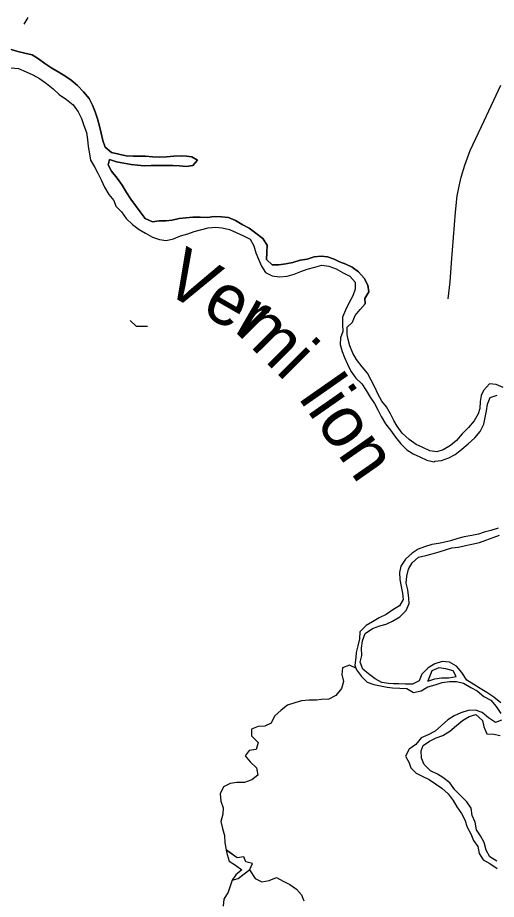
# Model space of a CAD drawing. Extents: x 0 to 34, y 0 to 22.
# Drawn here: x 6.124 to 7.011, y 8.561 to 10.195 of the extents above; entities that cross this region are included whole.
import ezdxf

# ---------------------------------------------------------------- set-up
doc = ezdxf.new("R2010")
doc.units = 0
for name, color, linetype in [('GM_X_City_Street', 7, 'Continuous'), ('GM_X_Major_River', 7, 'Continuous'), ('GM_X_Major_River_Text', 7, 'Continuous'), ('GM_X_Minor_Lake', 7, 'Continuous'), ('GM_X_Minor_River', 7, 'Continuous')]:
    doc.layers.add(name, color=color, linetype=linetype)

msp = doc.modelspace()

# ---------------------------------------------------------------- linework, layer by layer
at = {"layer": 'GM_X_City_Street'}
msp.add_line((6.1365, 10.1828), (6.144, 10.1951), dxfattribs=at)
for points in [[(6.9213, 9.674), (6.925, 9.7052), (6.9277, 9.7408), (6.9311, 9.7875), (6.9351, 9.8347), (6.9383, 9.8647), (6.9415, 9.8829), (6.9454, 9.8991), (6.9525, 9.9213), (6.962, 9.9489), (6.9882, 10.0038), (7.0189, 10.0702)], [(6.3327, 9.6337), (6.3439, 9.6234), (6.3648, 9.6231)]]:
    msp.add_lwpolyline(points, dxfattribs=at)
at = {"layer": 'GM_X_Major_River'}
for points in [[(6.7675, 9.6648), (6.767, 9.6743), (6.7742, 9.687), (6.7729, 9.6991), (6.7656, 9.712), (6.7552, 9.7241), (6.7434, 9.7327), (6.7316, 9.7379), (6.7201, 9.7424), (6.7106, 9.7473), (6.698, 9.7517), (6.6862, 9.7531), (6.6733, 9.7519), (6.6604, 9.7476), (6.6471, 9.7452), (6.6335, 9.7412), (6.6206, 9.7384), (6.6076, 9.7368), (6.5955, 9.7367), (6.5851, 9.7465), (6.5854, 9.7598), (6.5861, 9.7731), (6.578, 9.7856), (6.5653, 9.7954), (6.5527, 9.8048), (6.5397, 9.8119), (6.5275, 9.819), (6.5149, 9.8246), (6.5016, 9.826), (6.4879, 9.8267), (6.4758, 9.8246), (6.4621, 9.8253), (6.4488, 9.8255), (6.4359, 9.8239), (6.4233, 9.823), (6.4101, 9.8199), (6.3987, 9.8186), (6.3865, 9.8181), (6.374, 9.8165), (6.3606, 9.8228), (6.3514, 9.8353), (6.3422, 9.8466), (6.3341, 9.8587), (6.3256, 9.8712), (6.3175, 9.8848), (6.3087, 9.8977), (6.2983, 9.9102), (6.2918, 9.9223), (6.2943, 9.9318), (6.3073, 9.9277), (6.321, 9.9256), (6.3347, 9.9227), (6.3465, 9.9216), (6.3587, 9.9202), (6.3716, 9.9207), (6.3853, 9.9208), (6.3982, 9.921), (6.4115, 9.9207), (6.4237, 9.9201), (6.4366, 9.919), (6.4484, 9.921), (6.457, 9.931), (6.4467, 9.937), (6.4372, 9.9381), (6.4277, 9.9387), (6.4133, 9.9382), (6.4, 9.9373), (6.3874, 9.9365), (6.3737, 9.9371), (6.3612, 9.9381), (6.3509, 9.9384), (6.338, 9.9383), (6.3251, 9.9389), (6.3114, 9.9419), (6.298, 9.9448), (6.2865, 9.955), (6.2823, 9.9675), (6.2787, 9.9808), (6.276, 9.9941), (6.2724, 10.0073), (6.2678, 10.0206), (6.2631, 10.0331), (6.2565, 10.0452), (6.2465, 10.0577), (6.235, 10.069), (6.2232, 10.0792), (6.2117, 10.0871), (6.1995, 10.0946), (6.1876, 10.1017), (6.1746, 10.1103), (6.1632, 10.119), (6.1513, 10.1261), (6.1376, 10.129), (6.1247, 10.1323), (6.1121, 10.136)], [(6.1121, 10.136), (6.1247, 10.1323), (6.1376, 10.129), (6.1513, 10.1261), (6.1632, 10.119), (6.1746, 10.1103), (6.1876, 10.1017), (6.1995, 10.0946), (6.2117, 10.0871), (6.2232, 10.0792), (6.235, 10.069), (6.2465, 10.0577), (6.2565, 10.0452), (6.2631, 10.0331), (6.2678, 10.0206), (6.2724, 10.0073), (6.276, 9.9941), (6.2787, 9.9808), (6.2823, 9.9675), (6.2865, 9.955), (6.298, 9.9448), (6.3114, 9.9419), (6.3251, 9.9389), (6.338, 9.9383), (6.3509, 9.9384), (6.3612, 9.9381), (6.3737, 9.9371), (6.3874, 9.9365), (6.4, 9.9373), (6.4133, 9.9382), (6.4277, 9.9387), (6.4372, 9.9381), (6.4467, 9.937), (6.457, 9.931), (6.4484, 9.921), (6.4366, 9.919), (6.4237, 9.9201), (6.4115, 9.9207), (6.3982, 9.921), (6.3853, 9.9208), (6.3716, 9.9207), (6.3587, 9.9202), (6.3465, 9.9216), (6.3347, 9.9227), (6.321, 9.9256), (6.3073, 9.9277), (6.2943, 9.9318), (6.2918, 9.9223), (6.2983, 9.9102), (6.3087, 9.8977), (6.3175, 9.8848), (6.3256, 9.8712), (6.3341, 9.8587), (6.3422, 9.8466), (6.3514, 9.8353), (6.3606, 9.8228), (6.374, 9.8165), (6.3865, 9.8181), (6.3987, 9.8186), (6.4101, 9.8199), (6.4233, 9.823), (6.4359, 9.8239), (6.4488, 9.8255), (6.4621, 9.8253), (6.4758, 9.8246), (6.4879, 9.8267), (6.5016, 9.826), (6.5149, 9.8246), (6.5275, 9.819), (6.5397, 9.8119), (6.5527, 9.8048), (6.5653, 9.7954), (6.578, 9.7856), (6.5861, 9.7731), (6.5854, 9.7598), (6.5851, 9.7465), (6.5955, 9.7367), (6.6076, 9.7368), (6.6206, 9.7384), (6.6335, 9.7412), (6.6471, 9.7452), (6.6604, 9.7476), (6.6733, 9.7519), (6.6862, 9.7531), (6.698, 9.7517), (6.7106, 9.7473), (6.7201, 9.7424), (6.7316, 9.7379), (6.7434, 9.7327), (6.7552, 9.7241), (6.7656, 9.712), (6.7729, 9.6991), (6.7742, 9.687), (6.767, 9.6743), (6.7675, 9.6648)], [(6.1124, 10.1021), (6.1261, 10.1008), (6.1398, 10.0948), (6.1524, 10.0892), (6.165, 10.0825), (6.178, 10.0731), (6.1902, 10.0633), (6.2014, 10.0524), (6.2147, 10.0433), (6.227, 10.0332), (6.2366, 10.0203), (6.2424, 10.0082), (6.2471, 9.9953), (6.2517, 9.982), (6.2534, 9.9691), (6.2546, 9.9562), (6.2574, 9.9425), (6.2594, 9.9307), (6.2663, 9.9182), (6.2725, 9.9065), (6.2791, 9.8944), (6.2853, 9.8807), (6.2933, 9.8671), (6.3026, 9.8558), (6.3061, 9.8455), (6.3168, 9.835), (6.3253, 9.8229), (6.3371, 9.8116), (6.3494, 9.8026), (6.3612, 9.7954), (6.3742, 9.7883), (6.3868, 9.7839), (6.3993, 9.7821), (6.413, 9.7849), (6.4259, 9.7903), (6.4392, 9.7946), (6.4513, 9.7989), (6.4771, 9.8052), (6.4904, 9.8069), (6.5029, 9.8055), (6.5166, 9.8022), (6.5288, 9.797), (6.5422, 9.7906), (6.5548, 9.7843), (6.5614, 9.7718), (6.5653, 9.7592), (6.5699, 9.7471), (6.5757, 9.7346), (6.5831, 9.7225), (6.5956, 9.7165), (6.6093, 9.7147), (6.623, 9.716), (6.6363, 9.7196), (6.6484, 9.7246), (6.6605, 9.7285), (6.6746, 9.7328), (6.6875, 9.736), (6.7004, 9.7346), (6.7138, 9.7294), (6.7267, 9.7219), (6.7393, 9.7156), (6.7493, 9.7046), (6.749, 9.6917), (6.745, 9.6795), (6.7375, 9.6657), (6.7311, 9.6527), (6.7255, 9.6397), (6.726, 9.626), (6.7265, 9.6135), (6.722, 9.6012), (6.7214, 9.5891), (6.7249, 9.5762), (6.7292, 9.5648), (6.735, 9.5527), (6.7412, 9.5398), (6.7504, 9.5269), (6.7615, 9.5164), (6.7696, 9.5039), (6.7769, 9.4918), (6.785, 9.4797), (6.7912, 9.4683), (6.7974, 9.4554), (6.8054, 9.4422), (6.8143, 9.4301), (6.8239, 9.4172), (6.8335, 9.4048), (6.8446, 9.3938), (6.8568, 9.3863), (6.8691, 9.3807), (6.882, 9.3748), (6.8946, 9.3715)], [(6.1124, 10.1021), (6.1261, 10.1008), (6.1398, 10.0948), (6.1524, 10.0892), (6.165, 10.0825), (6.178, 10.0731), (6.1902, 10.0633), (6.2014, 10.0524), (6.2147, 10.0433), (6.227, 10.0332), (6.2366, 10.0203), (6.2424, 10.0082), (6.2471, 9.9953), (6.2517, 9.982), (6.2534, 9.9691), (6.2546, 9.9562), (6.2574, 9.9425), (6.2594, 9.9307), (6.2663, 9.9182), (6.2725, 9.9065), (6.2791, 9.8944), (6.2853, 9.8807), (6.2933, 9.8671), (6.3026, 9.8558), (6.3061, 9.8455), (6.3168, 9.835), (6.3253, 9.8229), (6.3371, 9.8116), (6.3494, 9.8026), (6.3612, 9.7954), (6.3742, 9.7883), (6.3868, 9.7839), (6.3993, 9.7821), (6.413, 9.7849), (6.4259, 9.7903), (6.4392, 9.7946), (6.4513, 9.7989), (6.4771, 9.8052), (6.4904, 9.8069), (6.5029, 9.8055), (6.5166, 9.8022), (6.5288, 9.797), (6.5422, 9.7906), (6.5548, 9.7843), (6.5614, 9.7718), (6.5653, 9.7592), (6.5699, 9.7471), (6.5757, 9.7346), (6.5831, 9.7225), (6.5956, 9.7165), (6.6093, 9.7147), (6.623, 9.716), (6.6363, 9.7196), (6.6484, 9.7246), (6.6605, 9.7285), (6.6746, 9.7328), (6.6875, 9.736), (6.7004, 9.7346), (6.7138, 9.7294), (6.7267, 9.7219), (6.7393, 9.7156), (6.7493, 9.7046), (6.749, 9.6917), (6.745, 9.6795), (6.7375, 9.6657), (6.7311, 9.6527), (6.7255, 9.6397), (6.726, 9.626), (6.7265, 9.6135), (6.722, 9.6012), (6.7214, 9.5891), (6.7249, 9.5762), (6.7292, 9.5648), (6.735, 9.5527), (6.7412, 9.5398), (6.7504, 9.5269), (6.7615, 9.5164), (6.7696, 9.5039), (6.7769, 9.4918), (6.785, 9.4797), (6.7912, 9.4683), (6.7974, 9.4554), (6.8054, 9.4422), (6.8143, 9.4301), (6.8239, 9.4172), (6.8335, 9.4048), (6.8446, 9.3938), (6.8568, 9.3863), (6.8691, 9.3807), (6.882, 9.3748), (6.8946, 9.3715)], [(7.0231, 9.5096), (7.0101, 9.5152), (6.9976, 9.5162), (6.9866, 9.504), (6.9825, 9.4944), (6.9803, 9.4837), (6.9801, 9.4704), (6.9771, 9.4605), (6.9696, 9.4475), (6.9591, 9.4352), (6.9474, 9.4233), (6.9365, 9.4114), (6.9255, 9.4018), (6.9123, 9.3937), (6.9005, 9.3902), (6.8872, 9.3919), (6.8746, 9.3979), (6.862, 9.4035), (6.849, 9.4133), (6.8364, 9.425), (6.8272, 9.4378), (6.821, 9.448), (6.8144, 9.4605), (6.8071, 9.4734), (6.7983, 9.4844), (6.7913, 9.498), (6.7855, 9.5101), (6.7789, 9.523), (6.772, 9.5359), (6.7624, 9.548), (6.7516, 9.5612), (6.7447, 9.5733), (6.7393, 9.5866), (6.7365, 9.5983), (6.7345, 9.6078), (6.7344, 9.6215), (6.7442, 9.6304), (6.7491, 9.6426), (6.7585, 9.6541), (6.7675, 9.6648)], [(6.8946, 9.3715), (6.8969, 9.373), (6.909, 9.3739), (6.9227, 9.3789), (6.9344, 9.3851), (6.9465, 9.3951), (6.9582, 9.4048), (6.9706, 9.4159), (6.9808, 9.4278), (6.9872, 9.4412), (6.9923, 9.4663), (6.9944, 9.4785), (6.9989, 9.4908), (7.0118, 9.4951)], [(7.0138, 9.2485), (7.0006, 9.2442), (6.9877, 9.241), (6.9778, 9.2375), (6.9649, 9.2351), (6.9512, 9.2327), (6.9391, 9.2292), (6.9258, 9.2252), (6.9129, 9.2221), (6.9034, 9.2205), (6.8909, 9.2181), (6.8777, 9.2141), (6.8659, 9.2099), (6.8549, 9.2021), (6.8425, 9.191), (6.8339, 9.1784), (6.8313, 9.1665), (6.8318, 9.1536), (6.8345, 9.1407), (6.8369, 9.1282), (6.8382, 9.1167), (6.831, 9.1045), (6.8189, 9.0975), (6.8068, 9.0887), (6.7936, 9.0825), (6.7811, 9.0751), (6.7694, 9.0682), (6.7581, 9.0563), (6.757, 9.0433), (6.7541, 9.0304), (6.7512, 9.0182), (6.7501, 9.0086), (6.7483, 8.9949)], [(6.8204, 8.9598), (6.8106, 8.9605), (6.7984, 8.9623), (6.7862, 8.9694), (6.7739, 8.9788), (6.7632, 8.9874), (6.7585, 9.0003), (6.7615, 9.0125), (6.7606, 9.0262), (6.7628, 9.0396), (6.7676, 9.0537), (6.7812, 9.0626), (6.7948, 9.0676), (6.8066, 9.0708), (6.8183, 9.0762), (6.8316, 9.0843), (6.8433, 9.0959), (6.8489, 9.1092), (6.8484, 9.1191), (6.8468, 9.1343), (6.8436, 9.1465), (6.8447, 9.1594), (6.848, 9.1728), (6.8547, 9.1846), (6.8664, 9.1946), (6.8797, 9.1982), (6.8918, 9.2013), (6.9047, 9.2049), (6.9184, 9.2092), (6.9282, 9.2123), (6.9404, 9.2136), (6.9533, 9.2164), (6.965, 9.2191), (6.9791, 9.2219), (6.9912, 9.2266), (7.0045, 9.2313), (7.0162, 9.2356)], [(6.7483, 8.9949), (6.7518, 8.9858), (6.7607, 8.9737), (6.7714, 8.9632), (6.7836, 8.9587), (6.7958, 8.9562), (6.8087, 8.9536), (6.8182, 8.9526), (6.8319, 8.9523), (6.8448, 8.9517), (6.8574, 8.9442), (6.8711, 8.9473), (6.8836, 8.9543), (6.8972, 8.9582), (6.9105, 8.9625), (6.9238, 8.9646), (6.9367, 8.9647), (6.9497, 8.9614), (6.963, 8.9531), (6.9749, 8.9471), (6.9871, 8.9366), (7.0001, 8.9299), (7.0105, 8.9178), (7.0189, 8.9049)], [(7.0188, 8.9251), (7.0058, 8.9352), (6.9932, 8.9439), (6.9805, 8.9514), (6.9687, 8.9589), (6.9561, 8.9668), (6.9465, 8.9808), (6.9365, 8.9928), (6.9239, 9.0003), (6.9102, 9.0017), (6.8965, 8.9974), (6.8841, 8.9897), (6.8724, 8.9782), (6.8675, 8.9659), (6.8554, 8.9594), (6.8421, 8.9596), (6.8299, 8.9599), (6.8204, 8.9598)], [(6.9208, 8.9711), (6.9226, 8.971), (6.9363, 8.9738), (6.9305, 8.9844), (6.9168, 8.9881), (6.9042, 8.9899), (6.8913, 8.9841), (6.8837, 8.9653)], [(6.9208, 8.9711), (6.9226, 8.971), (6.9363, 8.9738), (6.9305, 8.9844), (6.9168, 8.9881), (6.9042, 8.9899), (6.8913, 8.9841), (6.8838, 8.9654)], [(6.8837, 8.9653), (6.8964, 8.9696), (6.9089, 8.9713), (6.9208, 8.9711)], [(6.8839, 8.9653), (6.8964, 8.9696), (6.9089, 8.9713), (6.9208, 8.9711)], [(7.0202, 8.8928), (7.0088, 8.8885), (6.9962, 8.8971), (6.984, 8.9069), (6.9721, 8.9113), (6.9585, 8.9105), (6.9448, 8.9065), (6.9323, 8.9007), (6.9206, 8.8934), (6.8972, 8.8726), (6.8843, 8.8653), (6.8714, 8.8598), (6.8617, 8.8479), (6.8492, 8.8391), (6.8425, 8.8261), (6.849, 8.8139), (6.8525, 8.8041), (6.8621, 8.7943), (6.8743, 8.7883), (6.8861, 8.7827), (6.8976, 8.7748), (6.9098, 8.7666), (6.9213, 8.7564), (6.9306, 8.7439), (6.9371, 8.7322), (6.946, 8.7197), (6.9521, 8.708), (6.9568, 8.6943), (6.9634, 8.6818), (6.968, 8.6697), (6.9761, 8.6587), (6.9789, 8.6458), (6.9862, 8.6337), (6.9984, 8.627), (7.0118, 8.6176)], [(7.0117, 8.6316), (6.9987, 8.6391), (6.9918, 8.6516), (6.9878, 8.6657), (6.9809, 8.6782), (6.974, 8.6895), (6.9712, 8.7036), (6.9658, 8.7161), (6.9641, 8.7294), (6.9557, 8.7411), (6.9453, 8.752), (6.9338, 8.7637), (6.9242, 8.7766), (6.9112, 8.7864), (6.9013, 8.7924), (6.8887, 8.7991), (6.8772, 8.8104), (6.8718, 8.8225), (6.8716, 8.8358), (6.875, 8.8458), (6.8867, 8.8535), (6.8992, 8.8601), (6.9113, 8.8644), (6.9246, 8.8721), (6.9366, 8.8829), (6.948, 8.8921), (6.9601, 8.8994), (6.9726, 8.9034), (6.9852, 8.8924), (6.9872, 8.8803), (6.993, 8.8674), (7.0056, 8.8668), (7.0178, 8.8646)]]:
    msp.add_lwpolyline(points, dxfattribs=at)
at = {"layer": 'GM_X_Minor_Lake'}
for points in [[(6.5105, 8.6522), (6.5121, 8.6438), (6.516, 8.6313), (6.5275, 8.6238), (6.5393, 8.6155), (6.5284, 8.6063), (6.5216, 8.596), (6.5326, 8.5991), (6.5436, 8.6076), (6.5542, 8.6157)], [(6.5542, 8.6157), (6.5594, 8.6271), (6.5468, 8.6301), (6.5429, 8.6395), (6.5308, 8.6375), (6.5105, 8.6521)], [(6.5106, 8.652), (6.5121, 8.6438), (6.516, 8.6313), (6.5275, 8.6238), (6.5393, 8.6155), (6.5284, 8.6063), (6.5216, 8.596), (6.5326, 8.5991), (6.5436, 8.6076), (6.5542, 8.6157)], [(6.5542, 8.6157), (6.5594, 8.6271), (6.5468, 8.6301), (6.5429, 8.6395), (6.5308, 8.6375), (6.5106, 8.652)]]:
    msp.add_lwpolyline(points, dxfattribs=at)
at = {"layer": 'GM_X_Minor_River'}
for points in [[(6.7505, 8.9893), (6.7388, 8.9948), (6.7259, 8.9898), (6.7245, 8.9776), (6.7273, 8.9647), (6.7236, 8.9513), (6.7134, 8.9387), (6.7006, 8.9317), (6.6869, 8.9308), (6.6774, 8.93), (6.6633, 8.9298), (6.6497, 8.9286), (6.6375, 8.9247), (6.6239, 8.9203), (6.6122, 8.9111), (6.5997, 8.9003), (6.5937, 8.8873), (6.582, 8.8815), (6.5698, 8.881), (6.5573, 8.876), (6.5574, 8.8634), (6.5693, 8.8513), (6.566, 8.8384), (6.5531, 8.8364), (6.5456, 8.8268), (6.5548, 8.8154), (6.5667, 8.8045), (6.5691, 8.7908), (6.5577, 8.7824), (6.5441, 8.7769), (6.53, 8.7772), (6.5175, 8.7755), (6.5054, 8.7693), (6.4994, 8.756), (6.5007, 8.7423), (6.5049, 8.7305), (6.5043, 8.7183), (6.5006, 8.7046), (6.5037, 8.6917), (6.5073, 8.6788), (6.5078, 8.6651), (6.5105, 8.6522)], [(6.5533, 8.615), (6.5638, 8.599), (6.5764, 8.593), (6.5897, 8.5958), (6.6033, 8.6013), (6.6159, 8.5942), (6.6281, 8.5882), (6.6404, 8.5795), (6.65, 8.569), (6.6542, 8.5576)], [(6.5216, 8.596), (6.5138, 8.5738), (6.5063, 8.5608), (6.5049, 8.5479)]]:
    msp.add_lwpolyline(points, dxfattribs=at)

# ---------------------------------------------------------------- texts
at = {"layer": 'GM_X_Major_River_Text'}
for s, rotation, p in [('Ver', 329.9962, (6.3885, 9.6905)), ('mi', 314.9958, (6.526, 9.6135)), ('lion', 304.9957, (6.6429, 9.4902))]:
    msp.add_text(s, height=0.09475, rotation=rotation, dxfattribs=at).set_placement(p)

doc.saveas('drawing.dxf')
